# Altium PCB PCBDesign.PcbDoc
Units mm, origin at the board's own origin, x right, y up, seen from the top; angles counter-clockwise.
Board outline 78.74 x 65.02 mm, 2 copper layers (Top Layer, Bottom Layer); 12 components, 20 nets, 91 pads, 0 vias.
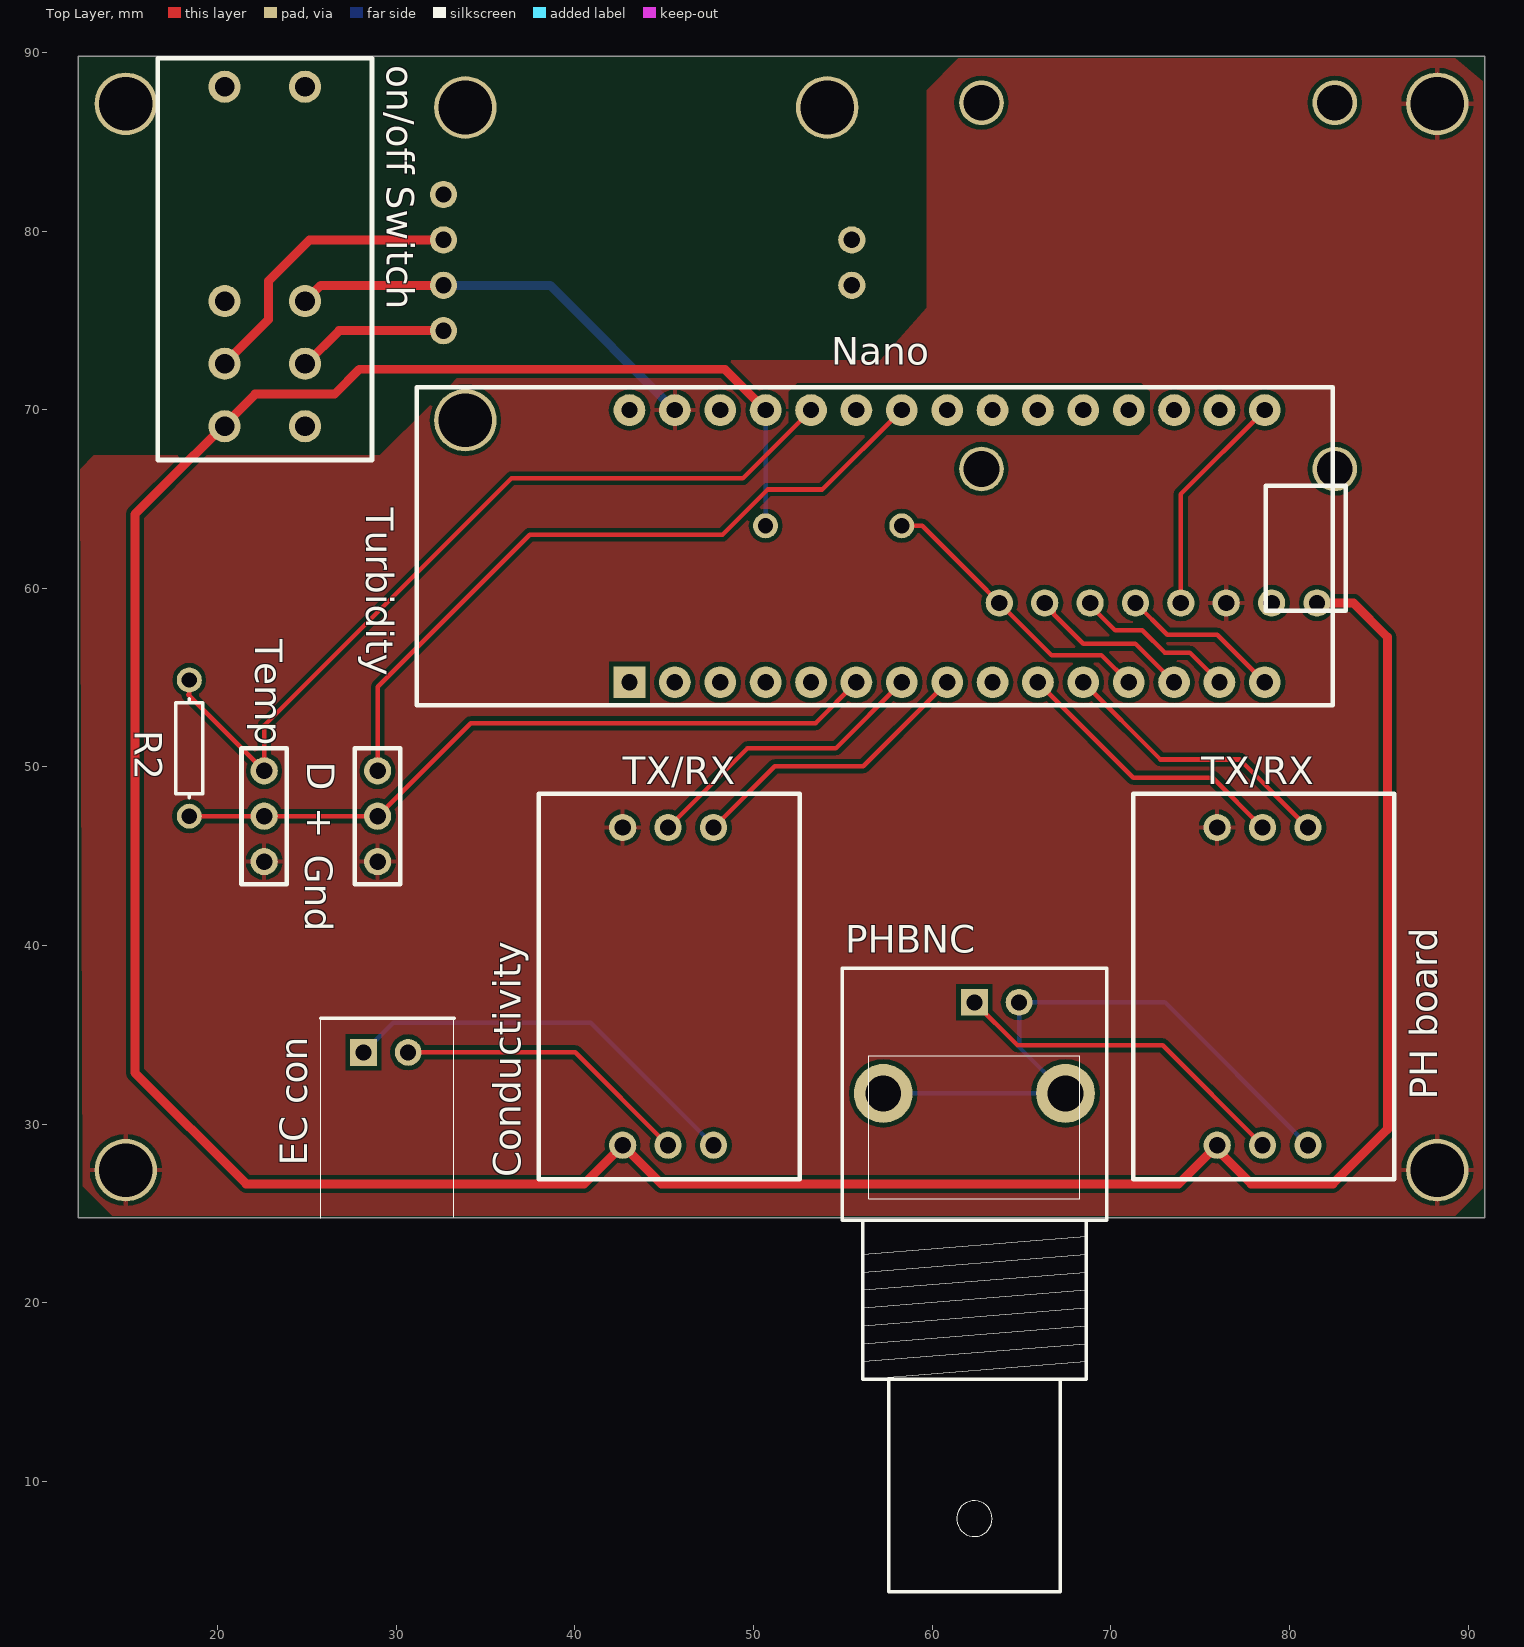
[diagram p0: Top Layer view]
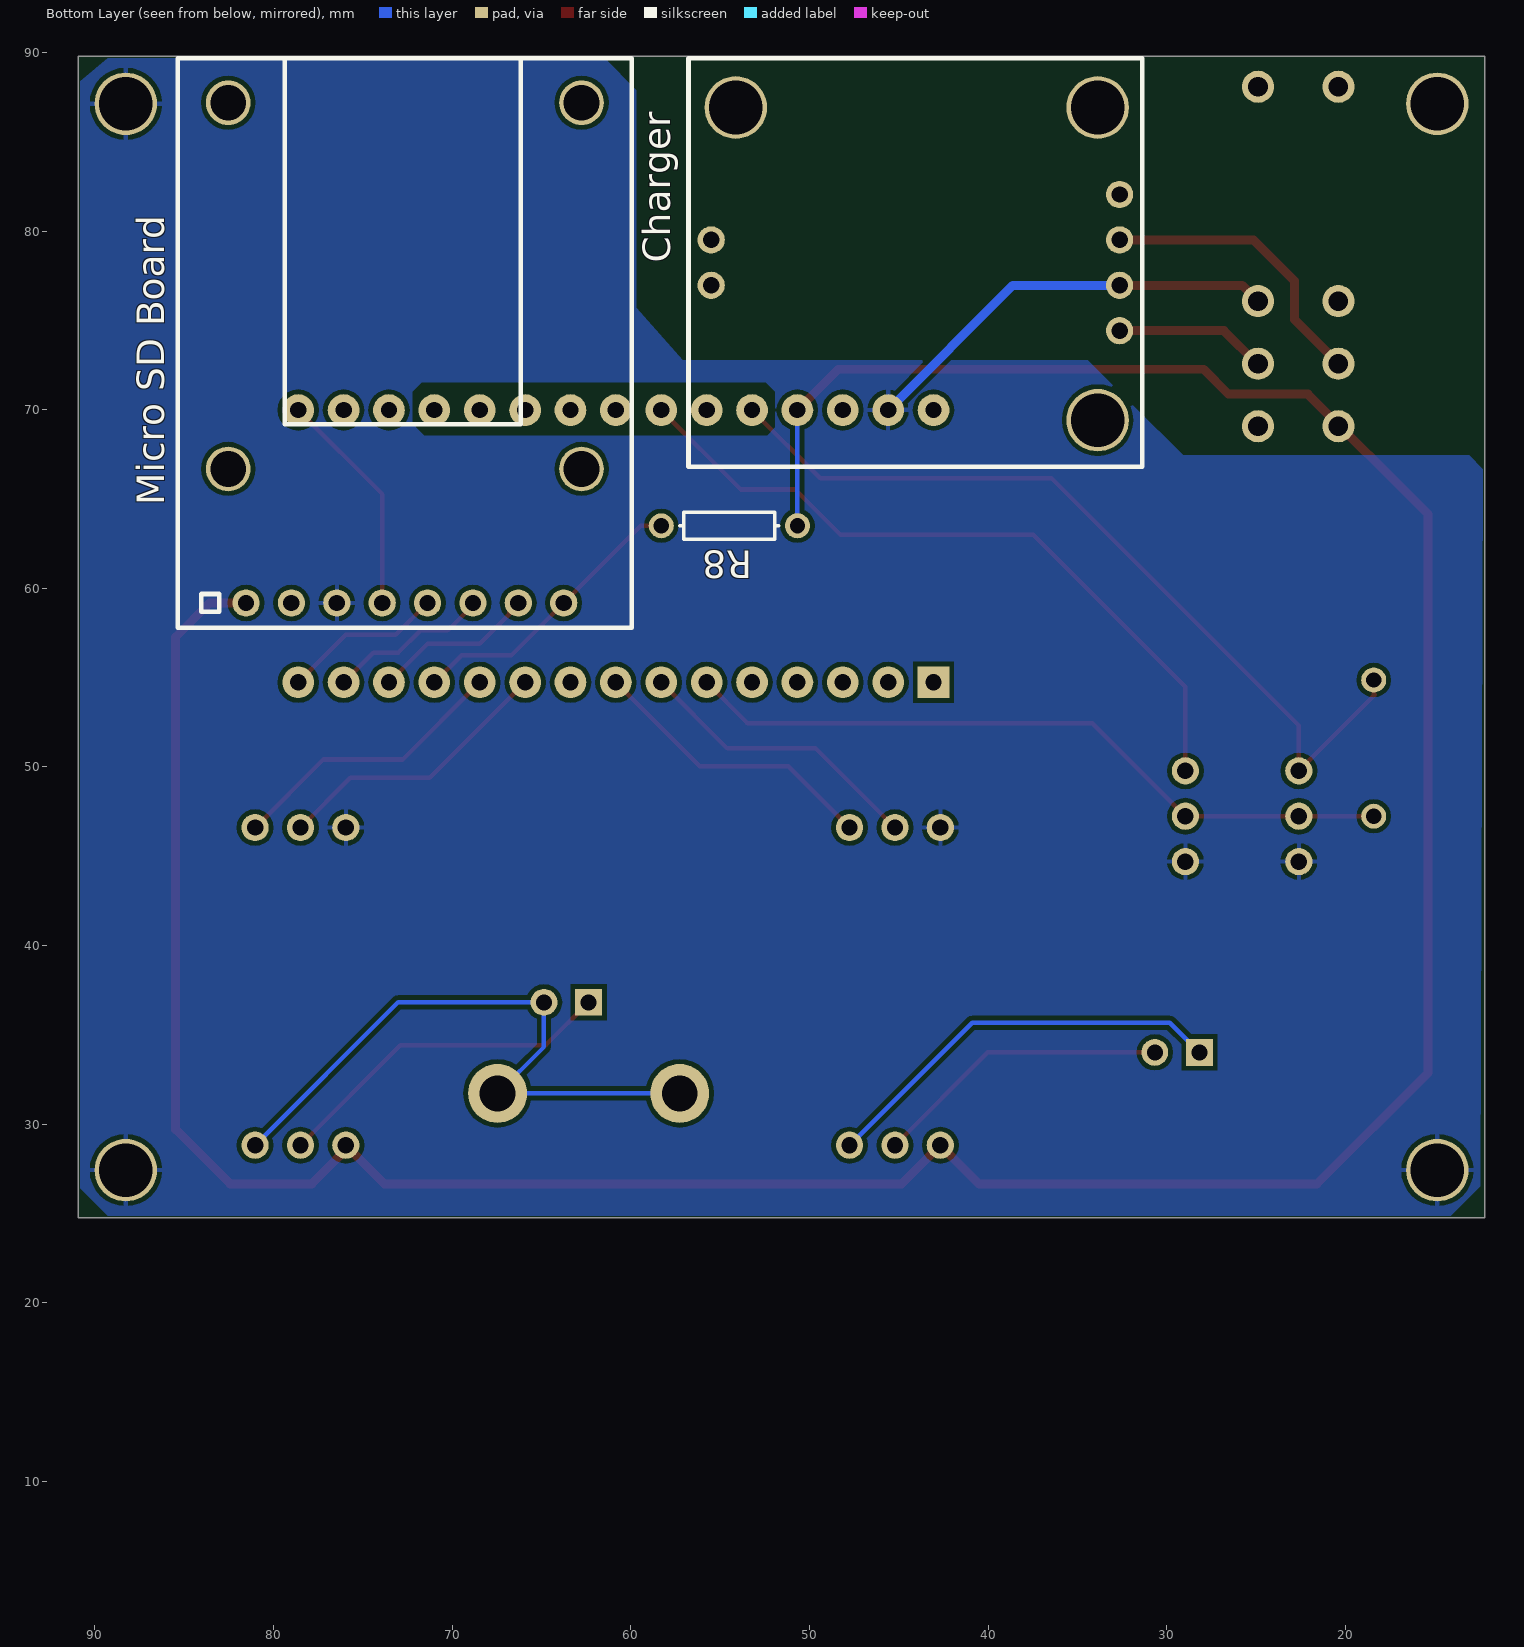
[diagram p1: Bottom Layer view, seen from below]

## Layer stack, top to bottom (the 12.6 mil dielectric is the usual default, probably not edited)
Top Solder: solder mask 0.0102, Solder Resist, Dk 3.5
Top Layer: signal copper 0.0356
Dielectric 1: dielectric 0.32, FR-4, Dk 4.8
Bottom Layer: signal copper 0.0356
Bottom Solder: solder mask 0.0102, Solder Resist, Dk 3.5

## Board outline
12.192,89.789 12.192,24.765 90.932,24.765 90.932,89.789

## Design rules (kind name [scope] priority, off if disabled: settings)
Clearance [All] p1: gap=0.254
HoleSize [All] p1: absolutevalues=TRUE maxlimit=5 minlimit=0.025 maxpercent=80.000 minpercent=20.000
MinimumAnnularRing [All] p1: minimumring=0.152
MinimumSolderMaskSliver [All] p1: minsoldermaskwidth=0.15
PolygonConnect [All] p1: connectstyle=Relief reliefconductorwidth=0.254 reliefentries=4 polygonreliefangle="90 Angle" airgapwidth=0.254
RoutingVias [All] p1: holewidth=0.711 width=1.27 viastyle="Through Hole" minholewidth=0.711 minwidth=1.27 maxholewidth=0.711 maxwidth=1.27
SilkToSilkClearance [All] p1: silktosilkclearance=0.2
SilkToSolderMaskClearance [IsPad] p1: minsilkscreentomaskgap=0.18 clearancetoexposedcopper=TRUE
SolderMaskExpansion [All] p1: expansion=0.102
Width 5v_in [InNet('VCC')] p1: maxlimit=0.51 minlimit=0.254 preferedwidth=0.5
Width [All] p2: maxlimit=0.5 minlimit=0.16 preferedwidth=0.254
26 further rules are at their usual default settings.

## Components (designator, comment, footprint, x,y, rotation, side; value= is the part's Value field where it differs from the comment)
Charger "Charger/Booster" CHARGER/BOOSTER 31.369,89.662 r270 bottom
Conductivity "Conductivity interfaceBoard" "CONDUCTIVITY INTERFACE BOARD - duplicate" 37.973,48.514 r0 top
"EC con" "Conductivity Connector" "Conductivity Connector (no BNC)" 28.18,34.031 r270 top
"Micro SD Board" "micro_sd" "Micro SD" 81.534,59.182 r270 bottom
Nano "nano" NANO 81.153,54.737 r90 top
"on/off Switch" "On/Off switch" "On/Off Switch" 24.892,76.073 r180 top
"PH board" "PH interfaceboard" "PH INTERFACE BOARD" 71.12,48.641 r0 top
PHBNC "BNC" "BNC_RA CON" 62.357,36.83 r90 top
R2 "Res2" AXIAL-0.3 18.415,51.054 r270 top
R8 "Res1" AXIAL-0.3 54.483,63.5 r0 bottom
Temp "TempSensorBoard" "TEMP HEADER" 22.606,47.244 r270 top
Turbidity "TurbiditySensor" "TURBIDTY HEADER" 28.956,47.244 r270 top

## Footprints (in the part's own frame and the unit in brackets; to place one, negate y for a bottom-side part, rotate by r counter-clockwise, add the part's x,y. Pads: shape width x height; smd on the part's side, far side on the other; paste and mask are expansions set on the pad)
AXIAL-0.3 [mm] "Axial Device, Thru-Hole; 2 Leads; 0.3 in Pin Spacing"
  round 1.4 hole 0.85: 1(-3.81,0) 2(3.81,0)
  silkscreen extent -2.77,-0.76 2.77,0.76
"BNC_RA CON" [mm] "Connector; BNC Elbow"
  rect 1.5x1.5 hole 0.9: 1(0,0)
  round 3.3 hole 2: 2(-5.1,-5.1) 2(-5.1,5.1)
  round 1.5 hole 0.9: 2(0,-2.5)
  silkscreen extent -33,-7.4 1.9,7.4
CHARGER/BOOSTER [mm]
  round 1.524 hole 0.914: 0(7.62,-1.27) 1(10.16,-1.27) 2(12.7,-1.27) 3(15.24,-1.27) 4(10.16,-24.13) 5(12.7,-24.13)
  round 3.5 hole 3: 10(2.75,-22.75) 10(2.75,-2.5) 10(20.25,-2.5)
  silkscreen extent 0,-25.4 22.86,0, body extent 0.13,-25.27 22.73,-0.13, height 11
"Conductivity Connector (no BNC)" [mm]
  rect 1.5x1.5 hole 0.9: 1(0.005,-0.014)
  round 1.5 hole 0.9: 2(0.005,2.486)
  silkscreen extent -1.9,-2.4 9.28,5.05
"CONDUCTIVITY INTERFACE BOARD - duplicate" [mil]
  round 60 hole 35.98: 0(185,-75) 1(285,-75) 2(385,-75) 3(185,-775) 4(285,-775) 5(385,-775)
  silkscreen extent 0,-850 575,0, body extent 5,-845 570,-5, height 433
"Micro SD" [mm]
  round 1.524 hole 0.914: 0(0,0) 1(0,2.54) 2(0,5.08) 3(0,7.62) 4(0,10.16) 5(0,12.7) 6(0,15.24) 7(0,17.78)
  round 2.5 hole 2 unplated: 10(-28,-1) 10(-28,18.78) 10(-7.5,-1) 10(-7.5,18.78)
  silkscreen extent -30.48,-3.81 1.4,21.59, body extent -30.48,-3.81 1.4,21.59, height 11
NANO [mil]
  rect 70x70 hole 36: 1(0,1500)
  round 70 hole 36: 2(0,1400) 3(0,1300) 4(0,1200) 5(0,1100) 6(0,1000) 7(0,900) 8(0,800) 9(0,700) 10(0,600) 11(0,500) 12(0,400) 13(0,300) 14(0,200) 15(0,100) 16(600,100) 17(600,200) 18(600,300) 19(600,400) 20(600,500) 21(600,600) 22(600,700) 23(600,800) 24(600,900) 25(600,1000) 26(600,1100) 27(600,1200) 28(600,1300) 29(600,1400) 30(600,1500)
  silkscreen extent -50,-79 650,1969, body extent -50,-79 650,1969, height 551
"On/Off Switch" [mm] "DPDT toggle switch"
  round 1.8 hole 1.1: 0(0,0) 1(0,3.5) 2(0,7) 3(4.5,0) 4(4.5,3.5) 5(4.5,7) 6(0,-12) 7(4.5,-12)
  silkscreen extent -3.75,-13.59 8.26,8.89
"PH INTERFACE BOARD" [mil]
  round 60 hole 35.98: 0(190,-80) 1(290,-80) 2(390,-80) 3(190,-780) 4(290,-780) 5(390,-780)
  silkscreen extent 5,-855 580,-5, body extent 10,-850 575,-10, height 433
"TEMP HEADER" [mil]
  round 60 hole 35.98: 0(-100,0) 1(0,0) 2(100,0)
  silkscreen extent -150,-50 150,50, body extent -145,-45 145,45, height 433
"TURBIDTY HEADER" [mil]
  round 60 hole 35.98: 0(-100,0) 1(0,0) 2(100,0)
  silkscreen extent -150,-50 150,50, body extent -145,-45 145,45, height 433

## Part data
PHBNC: "BNC Elbow Connector"
R2 R8: "Resistor"

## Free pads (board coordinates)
  round 3.5 hole 3: 100(14.859,27.432) 100(14.859,87.122) 100(88.265,27.432) 100(88.265,87.122)

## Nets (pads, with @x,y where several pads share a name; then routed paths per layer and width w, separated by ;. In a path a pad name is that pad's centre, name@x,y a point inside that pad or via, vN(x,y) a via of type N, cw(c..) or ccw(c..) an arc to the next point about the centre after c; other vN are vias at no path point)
"5V REGULATOR": "on/off Switch.4" Charger.1 | length 16.3
  Top Layer w0.5: 20.376,72.573 22.86,75.057 22.86,77.216 25.146,79.502 Charger.1@32.512,79.502
EC,RX: Conductivity.2 Nano.8 | length 16.4
  Top Layer w0.254: Conductivity.2 51.181,50.038 56.134,50.038 Nano.8
EC,TX: Conductivity.1 Nano.7 | length 16.4
  Top Layer w0.254: Conductivity.1 49.657,51.054 54.61,51.054 Nano.7
ENABLE: "on/off Switch.1" Charger.3 | length 8.4
  Top Layer w0.5: 24.892,72.573 24.948,72.573 26.797,74.422 Charger.3@32.512,74.422
GND: "Micro SD Board.2" "on/off Switch.0" "PH board.0" Charger.2 Conductivity.0 Nano.29 pad.100@14.859,27.432 pad.100@88.265,27.432 pad.100@88.265,87.122 Temp.2 Turbidity.2 | length 24
  Top Layer w0.5: 24.892,76.073 25.781,76.962 Charger.2@32.512,76.962
  Bottom Layer w0.5: Charger.2@32.512,76.962 38.608,76.962 Nano.29
"MICRO POWER": "Micro SD Board.0" "on/off Switch.5" "PH board.3" Conductivity.3 Nano.27 R8.1 | length 187.5
  Top Layer w0.5: Nano.27 48.387,72.263 27.94,72.263 26.543,70.866 22.098,70.866 15.367,64.135 15.367,32.893 21.59,26.67 40.513,26.67 Conductivity.3 44.831,26.67 73.787,26.67 75.946,28.829 75.946,28.575 77.851,26.67 82.423,26.67 85.471,29.718 85.471,57.277 83.566,59.182 81.534,59.182
  Bottom Layer w0.254: Nano.27 50.673,64.008 R8.1@51.181,63.5
NetConductivity_4: "EC con.2" Conductivity.4 | length 16.7
  Top Layer w0.254: 30.68,34.031 40.01,34.031 Conductivity.4
NetConductivity_5: "EC con.1" Conductivity.5 | length 23.1
  Bottom Layer w0.254: 28.18,34.031 29.836,35.687 40.894,35.687 Conductivity.5
"NetMicro SD Board_3": "Micro SD Board.3" Nano.16 | length 13
  Top Layer w0.254: 74.422,59.182 73.914,59.69 73.914,65.278 Nano.16
"NetMicro SD Board_4": "Micro SD Board.4" Nano.15 | length 9.1
  Top Layer w0.254: 71.374,59.182 73.152,57.404 75.946,57.404 Nano.15
"NetMicro SD Board_5": "Micro SD Board.5" Nano.14 | length 9.1
  Top Layer w0.254: 68.77,59.118 70.231,57.658 71.755,57.658 73.025,56.388 74.422,56.388 Nano.14
"NetMicro SD Board_6": "Micro SD Board.6" Nano.13 | length 8.9
  Top Layer w0.254: 66.802,59.182 66.802,58.547 68.453,56.896 71.374,56.896 Nano.13
"NetMicro SD Board_7": "Micro SD Board.7" Nano.12 R8.2 | length 16.3
  Top Layer w0.254: R8.2 59.436,63.5 66.675,56.261 69.469,56.261 Nano.12
NetPHBNC_1: "PH board.4" PHBNC.1 | length 19.4
  Top Layer w0.254: PHBNC.1 64.77,34.417 72.898,34.417 78.486,28.829
NetPHBNC_2: "PH board.5" PHBNC.2 | length 35.9
  Bottom Layer w0.254: PHBNC.2@57.257,31.73 67.457,31.73 64.857,34.33 64.857,36.83 73.025,36.83 81.026,28.829
PH,RX: "PH board.2" Nano.11 | length 15.9
  Top Layer w0.254: Nano.11 72.771,50.419 77.216,50.419 81.026,46.609
PH,TX: "PH board.1" Nano.10 | length 15.9
  Top Layer w0.254: Nano.10 71.247,49.403 75.692,49.403 78.486,46.609
SENSOR_POWER: Nano.6 R2.2 Temp.1 Turbidity.1 | length 40.4
  Top Layer w0.254: R2.2 Temp.1 Turbidity.1 34.163,52.451 53.467,52.451 Nano.6
"TEMP DATA": Nano.26 R2.1 Temp.0 | length 47.2
  Top Layer w0.254: 18.351,54.038 Temp.0 22.606,52.324 36.449,66.167 49.403,66.167 Nano.26 ; 18.415,54.102 R2.1
"TURB DATA": Nano.24 Turbidity.0 | length 40.5
  Top Layer w0.254: Turbidity.0 28.956,54.483 37.465,62.992 48.26,62.992 50.8,65.532 53.848,65.532 Nano.24
pads on no net: "Micro SD Board.1" "Micro SD Board.10" "on/off Switch.2" "on/off Switch.3" "on/off Switch.6" "on/off Switch.7" Charger.0 Charger.4 Charger.5 Charger.10 Nano.1 Nano.2 Nano.3 Nano.4 Nano.5 Nano.9 Nano.17 Nano.18 Nano.19 Nano.20 Nano.21 Nano.22 Nano.23 Nano.25 Nano.28 Nano.30

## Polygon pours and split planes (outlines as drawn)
GND on Top Layer "Gnd plane top 2" (solid, pour order 7): 14.097,24.892 13.208,25.781 12.446,26.543 12.319,66.675 13.081,67.437 28.575,67.437 29.083,67.437 34.417,72.771 57.094,72.771 59.69,75.692 59.69,87.884 61.468,89.662 89.281,89.662 90.805,88.392 90.805,73.66 90.805,72.136 90.805,26.416 90.551,26.162 89.281,24.892
GND on Bottom Layer "bottom GND-plane" (solid, remove dead copper, pour order 9): 14.097,24.892 13.208,25.781 12.446,26.543 12.319,66.675 13.081,67.437 28.575,67.437 29.083,67.437 34.417,72.771 57.094,72.771 59.69,75.692 59.69,87.884 61.468,89.662 89.281,89.662 90.805,88.392 90.805,73.66 90.805,72.136 90.805,26.416 90.551,26.162 89.281,24.892

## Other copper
Top Layer:
  pour cut-out: 71.691,71.501 72.199,70.993 72.199,69.215 71.565,68.58 52.365,68.58 51.943,69.002 51.943,70.993 52.451,71.501
  pour cut-out: 49.022,66.421 48.809,66.421 48.916,66.527
Bottom Layer:
  pour cut-out: 71.691,71.501 72.199,70.993 72.199,69.215 71.565,68.58 52.365,68.58 51.943,69.002 51.943,70.993 52.451,71.501

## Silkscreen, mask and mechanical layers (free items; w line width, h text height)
Top Overlay:
  text "D" at 25.019,50.292 h1.52 r270
  text "TX/RX" at 42.672,49.022 h1.52
  text "TX/RX" at 75.057,49.022 h1.52
  text "+" at 25.019,47.752 h1.52 r270
  text "Gnd" at 24.892,45.085 h1.52 r270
